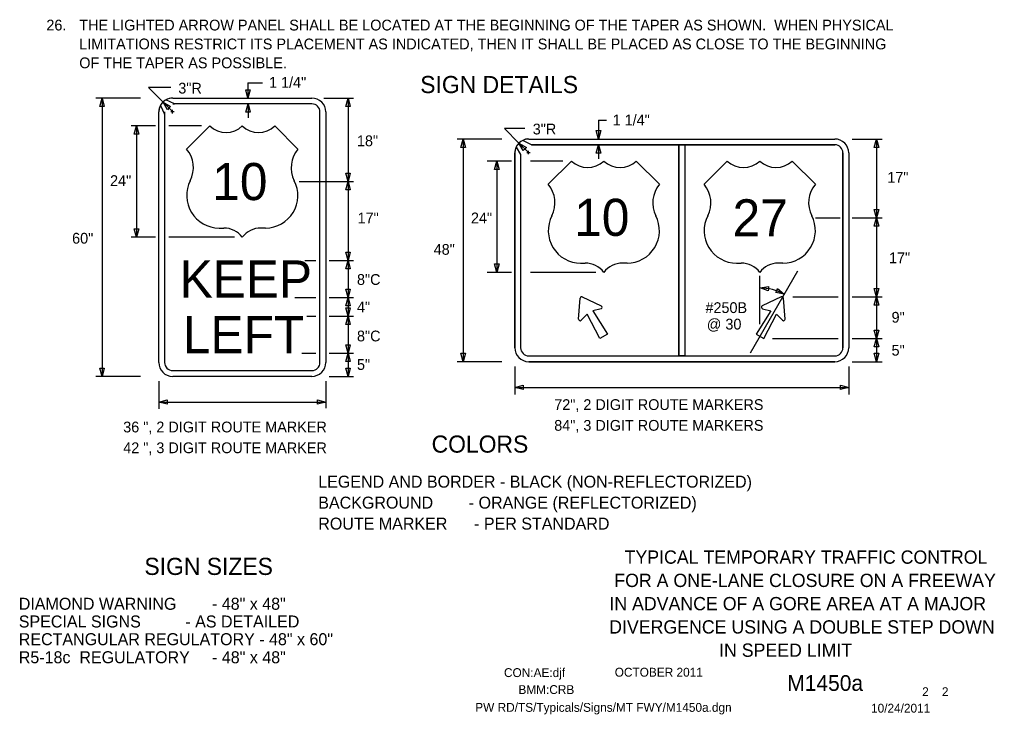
# Model space of a CAD drawing. Extents: x 16729 to 18464, y 5737 to 6974.
# Drawn here: x 17780 to 18464, y 5932 to 6419 of the extents above; entities that cross this region are included whole.
import ezdxf

# ---------------------------------------------------------------- set-up
doc = ezdxf.new("R2010")
doc.units = 0
for name, color, linetype in [('BORDER', 7, 'Continuous'), ('BORDER_SIGNAL_WO', 7, 'Continuous'), ('TRAFFIC_SIGNS_PR', 7, 'Continuous'), ('TYPICAL_EX', 7, 'Continuous'), ('TYPICAL_TEXT_DIMEN_PR', 7, 'Continuous')]:
    doc.layers.add(name, color=color, linetype=linetype)

msp = doc.modelspace()

# ---------------------------------------------------------------- linework, layer by layer
at = {"layer": 'TRAFFIC_SIGNS_PR'}
for p, q in [((17888.74, 6359.64), (17882.64, 6362.38)), ((17887.54, 6363.7), (17985.04, 6363.7)), ((17879.95, 6360.08), (17878.95, 6358.57)), ((17878.98, 6358.5), (17881.85, 6352.46)), ((17985.04, 6359.64), (17887.54, 6359.64)), ((17877.79, 6178.45), (17877.79, 6353.95)), ((17881.85, 6353.95), (17881.85, 6178.45)), ((17990.72, 6178.45), (17990.72, 6353.95)), ((17994.79, 6353.95), (17994.79, 6178.45)), ((18139.01, 6330.95), (18132.78, 6333.97)), ((18137.06, 6335), (18351.56, 6335)), ((18137.06, 6335), (18351.56, 6335)), ((18128.23, 6329.26), (18131.37, 6324.21)), ((18138.99, 6330.94), (18242.28, 6330.94)), ((18351.56, 6330.94), (18139, 6330.94)), ((18242.28, 6330.94), (18242.28, 6183.06)), ((18246.34, 6330.94), (18246.34, 6183.06)), ((18246.34, 6330.94), (18351.56, 6330.94)), ((18127.31, 6325.25), (18127.31, 6188.75)), ((18127.31, 6188.75), (18127.31, 6325.25)), ((18131.37, 6324.2), (18131.37, 6188.75)), ((18131.37, 6324.2), (18131.37, 6188.75)), ((18357.24, 6325.25), (18357.24, 6279.5)), ((18357.25, 6188.75), (18357.25, 6325.25)), ((18361.31, 6325.25), (18361.31, 6188.75)), ((18361.31, 6325.25), (18361.31, 6188.75)), ((18357.24, 6279.5), (18357.24, 6188.75)), ((18174.57, 6224.44), (18187.89, 6218.08)), ((18314.04, 6224.44), (18300.73, 6218.08)), ((18171.91, 6208.86), (18173.06, 6223.57)), ((18316.71, 6208.86), (18315.56, 6223.57)), ((18137.06, 6183.06), (18351.56, 6183.06)), ((18137.06, 6179), (18351.56, 6179)), ((18351.56, 6179), (18137.06, 6179)), ((17887.54, 6172.76), (17985.04, 6172.76)), ((17985.04, 6168.7), (17887.54, 6168.7))]:
    msp.add_line(p, q, dxfattribs=at)
for points in [[(18139, 6330.94), (18138.98, 6330.94)], [(18131.37, 6324.21), (18131.37, 6324.2)], [(18187.73, 6216.11), (18182, 6214.54), (18192.22, 6198.37), (18186.82, 6195.25), (18177.93, 6212.19), (18173.7, 6208.02)], [(18300.89, 6216.11), (18306.61, 6214.54), (18296.4, 6198.37), (18301.79, 6195.25), (18310.69, 6212.19), (18314.91, 6208.02)]]:
    msp.add_lwpolyline(points, dxfattribs=at)
msp.add_lwpolyline([(18242.28, 6330.94), (18246.34, 6330.94), (18246.34, 6183.06), (18242.28, 6183.06)], close=True, dxfattribs=at)
for centre, radius, start, end in [((17887.54, 6353.95), 9.75, 90, 180), ((17886.95, 6356.12), 7.6, 85.58319, 124.53531), ((17985.04, 6353.95), 9.75, 0, 90), ((17884.82, 6354.54), 7.06, 145.86811, 184.82317), ((17888.14, 6364.06), 4.47, 262.2432, 277.7568), ((17985.04, 6353.95), 5.69, 0, 90), ((17876.39, 6353.2), 5.51, 352.24294, 7.75653), ((18137.06, 6325.25), 9.75, 90, 180), ((18137.06, 6325.25), 9.75, 90, 180), ((18136.38, 6328.43), 6.6, 84.11162, 123.06374), ((18351.56, 6325.25), 9.75, 0, 90), ((18351.56, 6325.25), 9.75, 0, 90), ((18133.44, 6325.95), 6.17, 147.60925, 186.56283), ((18138, 6338.12), 7.24, 277.81035, 278.05403), ((18351.56, 6325.25), 5.69, 0, 89.99421), ((18351.56, 6325.25), 5.69, 0, 90), ((18174.12, 6223.49), 1.06, 64.48226, 175.51774), ((18314.5, 6223.49), 1.06, 4.48226, 115.51774), ((18187.43, 6217.13), 1.06, 285.9885, 64.48226), ((18301.18, 6217.13), 1.06, 115.51774, 254.0115), ((18172.97, 6208.78), 1.06, 175.51775, 314.01151), ((18315.65, 6208.78), 1.06, 225.98849, 4.48225), ((18137.06, 6188.75), 9.75, 180, 270), ((18137.06, 6188.75), 9.75, 180, 270), ((18137.06, 6188.75), 5.69, 180, 270), ((18137.06, 6188.75), 5.69, 180, 270), ((18351.56, 6188.75), 9.75, 270, 0), ((18351.56, 6188.75), 5.69, 270, 0), ((18351.56, 6188.75), 9.75, 270, 0), ((18351.56, 6188.75), 5.69, 270, 0), ((17887.54, 6178.45), 9.75, 180, 270), ((17887.54, 6178.45), 5.69, 180, 270), ((17985.04, 6178.45), 5.69, 270, 0), ((17985.04, 6178.45), 9.75, 270, 0)]:
    msp.add_arc(centre, radius, start, end, dxfattribs=at)
at = {"layer": 'TYPICAL_EX'}
for p, q in [((17897.29, 6327.95), (17913.54, 6344.2)), ((17975.29, 6327.95), (17959.04, 6344.2)), ((18150.67, 6303.34), (18166.92, 6319.59)), ((18228.67, 6303.34), (18212.42, 6319.59)), ((18259.95, 6303.34), (18276.2, 6319.59)), ((18337.95, 6303.34), (18321.7, 6319.59)), ((17920.01, 6272.66), (17923.26, 6272.66)), ((17952.56, 6272.66), (17949.31, 6272.66)), ((18173.4, 6248.05), (18176.65, 6248.05)), ((18205.94, 6248.05), (18202.69, 6248.05)), ((18282.67, 6248.05), (18285.92, 6248.05)), ((18315.22, 6248.05), (18311.97, 6248.05))]:
    msp.add_line(p, q, dxfattribs=at)
for centre, radius, start, end in [((17924.91, 6356.03), 16.42, 226.14041, 313.85958), ((17947.66, 6356.04), 16.42, 226.14042, 313.85959), ((17881.88, 6314.94), 20.16, 333.09768, 40.19361), ((17990.69, 6314.94), 20.16, 139.80639, 206.90233), ((18178.3, 6331.42), 16.42, 226.14041, 313.85958), ((18201.04, 6331.43), 16.42, 226.14042, 313.85959), ((18287.57, 6331.42), 16.42, 226.14041, 313.85958), ((18310.32, 6331.43), 16.42, 226.14042, 313.85959), ((17920.05, 6295.38), 22.73, 152.6698, 269.90132), ((17952.52, 6295.38), 22.73, 270.09868, 27.3302), ((18135.27, 6290.33), 20.16, 333.09768, 40.19361), ((18244.07, 6290.33), 20.16, 139.80639, 206.90233), ((18244.55, 6290.33), 20.16, 333.09768, 40.19361), ((18353.35, 6290.33), 20.16, 139.80639, 206.90233), ((18173.44, 6270.77), 22.73, 152.6698, 269.90132), ((18205.9, 6270.77), 22.73, 270.09868, 27.3302), ((18282.71, 6270.77), 22.73, 152.6698, 269.90132), ((18315.18, 6270.77), 22.73, 270.09868, 27.3302), ((17923.3, 6256.38), 16.28, 37.1038, 90.13853), ((17949.27, 6256.38), 16.28, 89.86147, 142.8962), ((18176.69, 6231.77), 16.28, 37.1038, 90.13853), ((18202.65, 6231.77), 16.28, 89.86147, 142.8962), ((18285.97, 6231.77), 16.28, 37.1038, 90.13853), ((18311.93, 6231.77), 16.28, 89.86147, 142.8962)]:
    msp.add_arc(centre, radius, start, end, dxfattribs=at)
at = {"layer": 'TYPICAL_TEXT_DIMEN_PR'}
for p, q in [((17886.16, 6370.98), (17870.5, 6370.98)), ((17870.5, 6370.98), (17880.74, 6360.74)), ((17940.26, 6363.7), (17938.69, 6369.56)), ((17938.69, 6369.56), (17940.26, 6369.56)), ((17940.26, 6374.46), (17940.26, 6363.7)), ((17940.26, 6374.46), (17950.36, 6374.46)), ((17940.26, 6369.56), (17941.83, 6369.56)), ((17941.83, 6369.56), (17940.26, 6363.7)), ((17864.96, 6363.7), (17833.66, 6363.7)), ((17836.43, 6357.84), (17838, 6363.7)), ((17838, 6363.7), (17838, 6168.7)), ((17838, 6363.7), (17839.57, 6357.84)), ((17993.33, 6363.7), (18014.29, 6363.7)), ((18008.82, 6357.84), (18010.39, 6363.7)), ((18010.39, 6363.7), (18010.39, 6305.2)), ((18010.39, 6363.7), (18011.96, 6357.84)), ((17838, 6357.84), (17836.43, 6357.84)), ((17839.57, 6357.84), (17838, 6357.84)), ((17880.74, 6360.74), (17887.3, 6354.19)), ((17883.77, 6355.49), (17880.74, 6360.74)), ((17880.74, 6360.74), (17885.99, 6357.71)), ((17884.88, 6356.6), (17883.77, 6355.49)), ((17885.99, 6357.71), (17884.88, 6356.6)), ((17886.09, 6354.19), (17888.5, 6354.19)), ((17887.3, 6352.98), (17887.3, 6355.4)), ((17938.74, 6353.77), (17940.31, 6359.64)), ((17940.31, 6359.64), (17940.31, 6349.89)), ((17940.31, 6359.64), (17941.88, 6353.77)), ((18010.39, 6357.84), (18008.82, 6357.84)), ((18011.96, 6357.84), (18010.39, 6357.84)), ((17940.31, 6353.77), (17938.74, 6353.77)), ((17941.88, 6353.77), (17940.31, 6353.77)), ((18185.92, 6348.15), (18185.92, 6335)), ((18185.92, 6348.15), (18191.44, 6348.15)), ((17875.41, 6344.2), (17858.29, 6344.2)), ((17860.61, 6338.34), (17862.18, 6344.2)), ((17862.18, 6344.2), (17862.18, 6266.2)), ((17862.18, 6344.2), (17863.75, 6338.34)), ((17907.65, 6344.2), (17884.78, 6344.2)), ((18134.2, 6342.28), (18120.02, 6342.28)), ((18120.02, 6342.28), (18130.17, 6332.14)), ((18185.92, 6335), (18184.34, 6340.86)), ((18184.34, 6340.86), (18185.92, 6340.86)), ((18185.92, 6340.86), (18187.49, 6340.86)), ((18187.49, 6340.86), (18185.92, 6335)), ((17862.18, 6338.34), (17860.61, 6338.34)), ((17863.75, 6338.34), (17862.18, 6338.34)), ((18118.08, 6335), (18086.78, 6335)), ((18089.55, 6329.14), (18091.12, 6335)), ((18091.12, 6335), (18091.12, 6179)), ((18091.12, 6335), (18092.69, 6329.14)), ((18363.68, 6335), (18384.64, 6335)), ((18379.17, 6329.14), (18380.74, 6335)), ((18380.74, 6335), (18380.74, 6279.75)), ((18380.74, 6335), (18382.31, 6329.14)), ((18091.12, 6329.14), (18089.55, 6329.14)), ((18092.69, 6329.14), (18091.12, 6329.14)), ((18130.17, 6332.14), (18136.82, 6325.49)), ((18133.21, 6326.88), (18130.17, 6332.14)), ((18130.17, 6332.14), (18135.43, 6329.1)), ((18134.32, 6327.99), (18133.21, 6326.88)), ((18135.43, 6329.1), (18134.32, 6327.99)), ((18184.39, 6325.07), (18185.96, 6330.94)), ((18184.39, 6325.07), (18185.96, 6330.94)), ((18185.96, 6330.94), (18185.96, 6321.19)), ((18185.96, 6330.94), (18187.53, 6325.07)), ((18185.96, 6330.94), (18187.53, 6325.07)), ((18380.74, 6329.14), (18379.17, 6329.14)), ((18382.31, 6329.14), (18380.74, 6329.14)), ((18135.61, 6325.49), (18138.03, 6325.49)), ((18136.82, 6324.28), (18136.82, 6326.7)), ((18185.96, 6325.07), (18184.39, 6325.07)), ((18185.96, 6325.07), (18184.39, 6325.07)), ((18187.53, 6325.07), (18185.96, 6325.07)), ((18187.53, 6325.07), (18185.96, 6325.07)), ((18124.94, 6319.59), (18107.81, 6319.59)), ((18113.1, 6313.73), (18114.67, 6319.59)), ((18114.67, 6313.73), (18113.1, 6313.73)), ((18114.67, 6319.59), (18114.67, 6241.59)), ((18114.67, 6319.59), (18116.25, 6313.73)), ((18116.25, 6313.73), (18114.67, 6313.73)), ((18161.04, 6319.59), (18138.16, 6319.59)), ((18010.39, 6305.2), (18008.82, 6311.06)), ((18008.82, 6311.06), (18010.39, 6311.06)), ((18010.39, 6311.06), (18011.96, 6311.06)), ((18011.96, 6311.06), (18010.39, 6305.2)), ((17976.18, 6305.2), (18014.29, 6305.2)), ((18008.82, 6299.34), (18010.39, 6305.2)), ((18010.39, 6305.2), (18010.39, 6249.95)), ((18010.39, 6305.2), (18011.96, 6299.34)), ((18010.39, 6299.34), (18008.82, 6299.34)), ((18011.96, 6299.34), (18010.39, 6299.34)), ((18338.12, 6279.75), (18355.27, 6279.75)), ((18363.68, 6279.75), (18384.64, 6279.75)), ((18380.74, 6279.75), (18379.17, 6285.61)), ((18379.17, 6285.61), (18380.74, 6285.61)), ((18379.17, 6273.89), (18380.74, 6279.75)), ((18380.74, 6285.61), (18382.31, 6285.61)), ((18382.31, 6285.61), (18380.74, 6279.75)), ((18380.74, 6279.75), (18380.74, 6224.5)), ((18380.74, 6279.75), (18382.31, 6273.89)), ((18380.74, 6273.89), (18379.17, 6273.89)), ((18382.31, 6273.89), (18380.74, 6273.89)), ((17875.41, 6266.2), (17858.29, 6266.2)), ((17862.18, 6266.2), (17860.61, 6272.06)), ((17860.61, 6272.06), (17862.18, 6272.06)), ((17862.18, 6272.06), (17863.75, 6272.06)), ((17863.75, 6272.06), (17862.18, 6266.2)), ((17930.78, 6266.2), (17884.78, 6266.2)), ((18010.39, 6249.95), (18008.82, 6255.81)), ((18008.82, 6255.81), (18010.39, 6255.81)), ((18010.39, 6255.81), (18011.96, 6255.81)), ((18011.96, 6255.81), (18010.39, 6249.95)), ((17980.11, 6249.95), (17987.8, 6249.95)), ((17997.16, 6249.95), (18014.29, 6249.95)), ((18008.82, 6244.09), (18010.39, 6249.95)), ((18010.39, 6249.95), (18010.39, 6223.95)), ((18010.39, 6249.95), (18011.96, 6244.09)), ((18114.67, 6241.59), (18113.1, 6247.45)), ((18113.1, 6247.45), (18114.67, 6247.45)), ((18114.67, 6247.45), (18116.25, 6247.45)), ((18116.25, 6247.45), (18114.67, 6241.59)), ((18010.39, 6244.09), (18008.82, 6244.09)), ((18011.96, 6244.09), (18010.39, 6244.09)), ((18124.94, 6241.59), (18107.81, 6241.59)), ((18184.16, 6241.59), (18138.16, 6241.59)), ((18292.34, 6185.1), (18325.58, 6242.69)), ((18299.1, 6205.25), (18299.1, 6239.25)), ((18299.12, 6230.69), (18305.12, 6231.65)), ((18305.12, 6231.65), (18304.96, 6230.09)), ((18010.39, 6223.95), (18008.82, 6229.81)), ((18008.82, 6229.81), (18010.39, 6229.81)), ((18010.39, 6229.81), (18011.96, 6229.81)), ((18011.96, 6229.81), (18010.39, 6223.95)), ((18304.8, 6228.53), (18299.12, 6230.69)), ((18304.96, 6230.09), (18304.8, 6228.53)), ((18310.11, 6227.37), (18310.79, 6228.78)), ((18316.08, 6226.24), (18310.11, 6227.37)), ((18310.79, 6228.78), (18311.48, 6230.2)), ((18311.48, 6230.2), (18316.08, 6226.24)), ((18322.05, 6224.5), (18353.92, 6224.5)), ((18363.68, 6224.5), (18384.64, 6224.5)), ((18380.74, 6224.5), (18379.17, 6230.36)), ((18379.17, 6230.36), (18380.74, 6230.36)), ((18379.17, 6218.64), (18380.74, 6224.5)), ((18380.74, 6230.36), (18382.31, 6230.36)), ((18382.31, 6230.36), (18380.74, 6224.5)), ((18380.74, 6224.5), (18380.74, 6195.25)), ((18380.74, 6224.5), (18382.31, 6218.64)), ((17973.1, 6223.95), (17987.8, 6223.95)), ((17997.16, 6223.95), (18014.29, 6223.95)), ((18008.82, 6218.09), (18010.39, 6223.95)), ((18010.39, 6218.09), (18008.82, 6218.09)), ((18010.39, 6223.95), (18010.39, 6210.95)), ((18010.39, 6223.95), (18011.96, 6218.09)), ((18011.96, 6218.09), (18010.39, 6218.09)), ((18380.74, 6218.64), (18379.17, 6218.64)), ((18382.31, 6218.64), (18380.74, 6218.64)), ((17981.45, 6210.95), (17987.8, 6210.95)), ((17997.16, 6210.95), (18014.29, 6210.95)), ((18010.39, 6210.95), (18008.82, 6216.81)), ((18008.82, 6216.81), (18010.39, 6216.81)), ((18008.82, 6205.09), (18010.39, 6210.95)), ((18010.39, 6216.81), (18011.96, 6216.81)), ((18011.96, 6216.81), (18010.39, 6210.95)), ((18010.39, 6210.95), (18010.39, 6184.95)), ((18010.39, 6210.95), (18011.96, 6205.09)), ((18010.39, 6205.09), (18008.82, 6205.09)), ((18011.96, 6205.09), (18010.39, 6205.09)), ((18380.74, 6195.25), (18379.17, 6201.11)), ((18379.17, 6201.11), (18380.74, 6201.11)), ((18380.74, 6201.11), (18382.31, 6201.11)), ((18382.31, 6201.11), (18380.74, 6195.25)), ((18010.39, 6184.95), (18008.82, 6190.81)), ((18008.82, 6190.81), (18010.39, 6190.81)), ((18010.39, 6190.81), (18011.96, 6190.81)), ((18011.96, 6190.81), (18010.39, 6184.95)), ((18307.91, 6195.25), (18353.92, 6195.25)), ((18363.68, 6195.25), (18384.64, 6195.25)), ((18379.17, 6189.39), (18380.74, 6195.25)), ((18380.74, 6195.25), (18380.74, 6179)), ((18380.74, 6195.25), (18382.31, 6189.39)), ((17977.95, 6184.95), (17987.8, 6184.95)), ((17997.16, 6184.95), (18014.29, 6184.95)), ((18008.82, 6179.09), (18010.39, 6184.95)), ((18010.39, 6184.95), (18010.39, 6168.7)), ((18010.39, 6184.95), (18011.96, 6179.09)), ((18091.12, 6179), (18089.55, 6184.86)), ((18089.55, 6184.86), (18091.12, 6184.86)), ((18091.12, 6184.86), (18092.69, 6184.86)), ((18092.69, 6184.86), (18091.12, 6179)), ((18380.74, 6189.39), (18379.17, 6189.39)), ((18380.74, 6179), (18379.17, 6184.86)), ((18379.17, 6184.86), (18380.74, 6184.86)), ((18382.31, 6189.39), (18380.74, 6189.39)), ((18380.74, 6184.86), (18382.31, 6184.86)), ((18382.31, 6184.86), (18380.74, 6179)), ((18010.39, 6179.09), (18008.82, 6179.09)), ((18011.96, 6179.09), (18010.39, 6179.09)), ((18118.08, 6179), (18086.78, 6179)), ((18363.68, 6179), (18380.81, 6179)), ((18363.68, 6179), (18384.64, 6179)), ((18363.68, 6179), (18380.81, 6179)), ((17838, 6168.7), (17836.43, 6174.56)), ((17836.43, 6174.56), (17838, 6174.56)), ((17838, 6174.56), (17839.57, 6174.56)), ((17839.57, 6174.56), (17838, 6168.7)), ((18010.39, 6168.7), (18008.82, 6174.56)), ((18008.82, 6174.56), (18010.39, 6174.56)), ((18010.39, 6174.56), (18011.96, 6174.56)), ((18011.96, 6174.56), (18010.39, 6168.7)), ((18127.31, 6175.65), (18127.31, 6156.09)), ((18361.31, 6175.65), (18361.31, 6156.09)), ((17864.96, 6168.7), (17833.66, 6168.7)), ((17877.79, 6165.35), (17877.79, 6146)), ((17994.79, 6165.35), (17994.79, 6146.46)), ((17997.16, 6168.7), (18014.29, 6168.7)), ((18127.31, 6161.03), (18133.17, 6162.6)), ((18127.31, 6161.03), (18361.31, 6161.03)), ((18133.17, 6159.46), (18127.31, 6161.03)), ((18133.17, 6162.6), (18133.17, 6161.03)), ((18133.17, 6161.03), (18133.17, 6159.46)), ((18355.45, 6161.03), (18355.45, 6162.6)), ((18355.45, 6162.6), (18361.31, 6161.03)), ((18361.31, 6161.03), (18355.45, 6159.46)), ((18355.45, 6159.46), (18355.45, 6161.03)), ((17877.79, 6150.73), (17883.65, 6152.3)), ((17877.79, 6150.73), (17994.79, 6150.73)), ((17883.65, 6149.15), (17877.79, 6150.73)), ((17883.65, 6152.3), (17883.65, 6150.73)), ((17883.65, 6150.73), (17883.65, 6149.15)), ((17988.92, 6150.73), (17988.92, 6152.3)), ((17988.92, 6152.3), (17994.79, 6150.73)), ((17994.79, 6150.73), (17988.92, 6149.15)), ((17988.92, 6149.15), (17988.92, 6150.73))]:
    msp.add_line(p, q, dxfattribs=at)
msp.add_arc((18299.29, 6196.25), 34.39, 60.74521, 90.32117, dxfattribs=at)

# ---------------------------------------------------------------- texts
at = {"layer": 'BORDER'}
for s, p in [('TYPICAL TEMPORARY TRAFFIC CONTROL', (18204.21, 6037.44)), ('FOR A ONE-LANE CLOSURE ON A FREEWAY', (18196.99, 6021.14)), ('IN ADVANCE OF A GORE AREA AT A MAJOR', (18193.54, 6004.84)), ('DIVERGENCE USING A DOUBLE STEP DOWN ', (18193.42, 5988.54)), ('IN SPEED LIMIT', (18270.42, 5972.24))]:
    msp.add_text(s, height=9.3, dxfattribs=at).set_placement(p)
at = {"layer": 'BORDER_SIGNAL_WO'}
for s, height, p in [('CON:AE:djf  ', 6.2, (18119.69, 5958.06)), ('    OCTOBER 2011    ', 6.2, (18188.08, 5958.34)), ('    M1450a   ', 11, (18301.86, 5948.38)), ('BMM:CRB   ', 6.2, (18129.81, 5946.17)), (' 2    2 ', 6.2, (18410.45, 5944.7)), ('PW RD/TS/Typicals/Signs/MT FWY/M1450a.dgn      ', 6.2, (18099.55, 5933.71)), ('10/24/2011    ', 6.2, (18376.93, 5933.13))]:
    msp.add_text(s, height=height, dxfattribs=at).set_placement(p)
at = {"layer": 'TRAFFIC_SIGNS_PR'}
for s, p in [('10', (17915.26, 6292.2)), ('10', (18168.91, 6267.13)), ('27', (18279.91, 6266.77)), ('KEEP', (17892.39, 6223.95)), ('LEFT', (17894.62, 6184.95))]:
    msp.add_text(s, height=26, dxfattribs=at).set_placement(p)
at = {"layer": 'TYPICAL_TEXT_DIMEN_PR'}
for s, height, p in [('26.', 7.56, (17798.98, 6411.04)), ('THE LIGHTED ARROW PANEL SHALL BE LOCATED AT THE BEGINNING OF THE TAPER AS SHOWN.  WHEN PHYSICAL', 7.56, (17822.03, 6411.04)), ('LIMITATIONS RESTRICT ITS PLACEMENT AS INDICATED, THEN IT SHALL BE PLACED AS CLOSE TO THE BEGINNING', 7.56, (17822.03, 6397.81)), ('OF THE TAPER AS POSSIBLE.', 7.56, (17822.03, 6384.58)), ('1 1/4"', 7.55, (17955.06, 6370.95)), ('SIGN DETAILS', 12, (18061.01, 6367.17)), ('3"R', 7.55, (17891.42, 6366.86)), ('1 1/4"', 7.55, (18195.84, 6344.57)), ('3"R', 7.55, (18139.84, 6338.2)), ('18"', 7.55, (18016.63, 6329.97)), ('24"', 7.55, (17843.63, 6302.08)), ('17"', 7.55, (18388.32, 6304.36)), ('17"', 7.55, (18017.08, 6275.92)), ('24"', 7.55, (18096.53, 6275.92)), ('60"', 7.55, (17817.03, 6261.71)), ('48"', 7.55, (18070.42, 6253.9)), ('17"', 7.55, (18389.52, 6248)), ('8"C', 7.55, (18016.66, 6232.8)), ('4" ', 7.55, (18016.66, 6213.54)), ('#250B', 7.55, (18260.87, 6213.09)), ('9"', 7.55, (18391.3, 6206.34)), ('@ 30', 7.55, (18261.81, 6201.54)), ('8"C', 7.55, (18016.66, 6193.22)), ('5"', 7.55, (18391.3, 6183.24)), ('5" ', 7.55, (18016.66, 6173.24)), ('72", 2 DIGIT ROUTE MARKERS', 7.55, (18154.89, 6145.16)), ('36 ", 2 DIGIT ROUTE MARKER', 7.55, (17852.83, 6129.46)), ('84", 3 DIGIT ROUTE MARKERS', 7.55, (18154.89, 6130.61)), ('42 ", 3 DIGIT ROUTE MARKER', 7.55, (17852.83, 6114.91)), ('COLORS', 12, (18068.95, 6115.28)), ('LEGEND AND BORDER - BLACK (NON-REFLECTORIZED)', 8.4, (17989.53, 6090.75)), ('BACKGROUND        - ORANGE (REFLECTORIZED)', 8.4, (17989.53, 6076.05)), ('ROUTE MARKER      - PER STANDARD', 8.4, (17989.53, 6061.35)), ('SIGN SIZES', 12, (17867.69, 6029.59)), ('DIAMOND WARNING        - 48" x 48"', 8.4, (17779.65, 6005.19)), ('SPECIAL SIGNS          - AS DETAILED', 8.4, (17779.65, 5992.79)), ('RECTANGULAR REGULATORY - 48" x 60"', 8.4, (17779.65, 5980.39)), ('R5-18c  REGULATORY     - 48" x 48"', 8.4, (17779.65, 5967.74))]:
    msp.add_text(s, height=height, dxfattribs=at).set_placement(p)

doc.saveas('drawing.dxf')
